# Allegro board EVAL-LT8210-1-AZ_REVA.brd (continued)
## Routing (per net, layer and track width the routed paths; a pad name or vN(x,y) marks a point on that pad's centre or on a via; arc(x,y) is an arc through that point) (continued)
VDD: length 538.3
  TOP w0.635: v2(102.26,104.34) D3.C ; v2(102.26,17.09) D1.C ; v2(102.26,194.13) D5.C ; v2(102.26,283.92) D7.C
  TOP w0.762: RPWGD4.2 47.84,285.54 v1(46.23,283.92) ; v1(46.22,104.33) 47.88,105.99 RPWGD2.2 ; RPWGD3.2 47.85,195.78 v1(46.2,194.13)
  L3_SIG w0.508: v1(46.23,283.92) 46.22,283.91 46.22,194.14 v1(46.2,194.13) 46.22,194.12 v1(46.22,104.33) 46.22,23.36 v2(46.99,22.58)
  L5_VCC w0.508: 46.99,18.08 v2(46.99,22.58) 46.99,29.34 48.77,31.11 v2(52.02,31.11) ; 46.99,18.08 46.99,13.51 ; 46.99,18.08 49.51,18.08 51.23,16.36 JP2.1 ; 46.99,13.51 49.3,13.51 JP1.1 ; 46.99,13.51 46.99,10.74 50.16,7.57 92.73,7.57 v2(102.26,17.09) ; v2(102.26,283.92) 49.25,283.92 v1(46.23,283.92) ; v1(46.22,104.33) 46.88,104.33 46.89,104.34 v2(102.26,104.34) ; v1(46.2,194.13) v2(102.26,194.13)
VIN: length 383.1
  TOP w0.203: L5.1 74.76,90.94 18.16,90.94 P2.1
  TOP w0.508: 28.96,315.25 v2(28.96,316.51) ; 28.96,48.43 28.97,48.44 29.22,48.44 v2(29.22,49.68) ; 28.96,225.46 v2(28.96,226.72) ; v2(28.96,136.65) 28.96,135.65
  TOP w0.61: v2(102.76,200.75) 103.75,200.75 103.76,200.76 RIN3.2 ; RIN1.2 103.76,23.72 103.75,23.71 v2(102.76,23.71) ; v2(102.76,110.96) 103.75,110.96 103.76,110.97 RIN2.2 ; RIN4.2 103.76,290.55 103.75,290.54 v2(102.76,290.54)
  TOP w0.635: REN5.2 103.9,199.13 RIN3.2 ; REN1.2 103.9,22.1 RIN1.2 ; RIN2.2 103.9,109.35 REN3.2 ; REN7.2 103.9,288.92 RIN4.2
  L5_VCC w0.61: 31.62,121.77 91.95,121.77 v2(102.76,110.96) ; 31.55,37.53 88.94,37.53 v2(102.76,23.71) ; v2(102.76,200.75) 91.95,211.56 31.6,211.56 ; v2(102.76,290.54) 91.95,301.35 31.7,301.35
  vias: v2(7.57,273.69) v2(7.57,94.36) v2(8,276.13) v2(8,271.24) v2(8,96.81) v2(8,91.91) v2(9.24,278.29) v2(9.24,269.08) v2(9.24,98.97) v2(9.24,89.76) v2(11.15,279.89) v2(11.15,267.48) v2(11.15,100.56) v2(11.15,88.16) v2(13.49,280.74) v2(13.49,266.63) v2(13.49,101.42) v2(13.49,87.31) v2(15.98,280.74) v2(15.98,266.63) v2(15.98,101.42) v2(15.98,87.31) v2(18.31,279.89) v2(18.31,267.48) v2(18.31,100.56) v2(18.31,88.16) v2(20.22,278.29) v2(20.22,269.08) v2(20.22,98.97) v2(20.22,89.76) v2(21.46,276.13) v2(21.46,271.24) v2(21.46,96.81) v2(21.46,91.91) v2(21.89,273.69) v2(21.89,94.36) v2(24.77,241.68) v2(24.77,240.54) v2(24.77,239.4) v2(24.77,238.25) v2(24.77,237.11) v2(24.77,235.97) v2(24.77,234.82) v2(24.77,233.68) v2(24.77,232.54) v2(24.77,231.39) v2(24.77,230.25) v2(24.77,229.11) v2(24.77,227.97) v2(24.77,226.82) v2(24.77,225.68) v2(24.77,224.54) v2(24.83,331.47) v2(24.83,330.33) v2(24.83,329.18) v2(24.83,328.04) v2(24.83,326.9) v2(24.83,325.75) v2(24.83,324.61) v2(24.83,323.47) v2(24.83,322.33) v2(24.83,321.18) v2(24.83,320.04) v2(24.83,318.9) v2(24.83,317.75) v2(24.83,316.61) v2(24.83,315.47) v2(24.83,314.32) v2(24.89,151.26) v2(24.89,150.11) v2(24.89,148.97) v2(24.89,147.83) v2(24.89,146.69) v2(24.89,145.54) v2(24.89,144.4) v2(24.89,143.26) v2(24.89,142.11) v2(24.89,140.97) v2(24.89,139.83) v2(24.89,138.68) v2(24.89,137.54) v2(24.89,136.4) v2(24.89,135.26) v2(24.89,134.11) v2(24.8,64.01) v2(24.8,62.87) v2(24.8,61.72) v2(24.8,60.58) v2(24.8,59.44) v2(24.8,58.29) v2(24.8,57.15) v2(24.8,56.01) v2(24.8,54.86) v2(24.8,53.72) v2(24.8,52.58) v2(24.8,51.44) v2(24.8,50.29) v2(24.8,49.15) v2(24.8,48.01) v2(24.8,46.86) v2(25.97,331.47) v2(25.97,330.33) v2(25.97,329.18) v2(25.97,328.04) v2(25.97,326.9) v2(25.97,325.75) v2(25.97,324.61) v2(25.97,323.47) v2(25.97,322.33) v2(25.97,321.18) v2(25.97,320.04) v2(25.97,318.9) v2(25.97,317.75) v2(25.97,316.61) v2(25.97,315.47) v2(25.97,314.32) v2(25.91,241.68) v2(25.91,240.54) v2(25.91,239.4) v2(25.91,238.25) v2(25.91,237.11) v2(25.91,235.97) v2(25.91,234.82) v2(25.91,233.68) v2(25.91,232.54) v2(25.91,231.39) v2(25.91,230.25) v2(25.91,229.11) v2(25.91,227.97) v2(25.91,226.82) v2(25.91,225.68) v2(25.91,224.54) v2(25.95,64.01) v2(25.95,62.87) v2(25.95,61.72) v2(25.95,60.58) v2(25.95,59.44) v2(25.95,58.29) v2(25.95,57.15) v2(25.95,56.01) v2(25.95,54.86) v2(25.95,53.72) v2(25.95,52.58) v2(25.95,51.44) v2(25.95,50.29) v2(25.95,49.15) v2(25.95,48.01) v2(25.95,46.86) v2(26.03,151.26) v2(26.03,150.11) v2(26.03,148.97) v2(26.03,147.83) v2(26.03,146.69) v2(26.03,145.54) v2(26.03,144.4) v2(26.03,143.26) v2(26.03,142.11) v2(26.03,140.97) v2(26.03,139.83) v2(26.03,138.68) v2(26.03,137.54) v2(26.03,136.4) v2(26.03,135.26) v2(26.03,134.11) v2(27.05,241.68) v2(27.05,240.54) v2(27.05,239.4) v2(27.05,238.25) v2(27.05,237.11) v2(27.05,235.97) v2(27.05,234.82) v2(27.05,233.68) v2(27.05,232.54) v2(27.05,231.39) v2(27.05,230.25) v2(27.05,229.11) v2(27.05,227.97) v2(27.05,226.82) v2(27.05,225.68) v2(27.05,224.54) v2(27.09,64.01) v2(27.09,62.87) v2(27.09,61.72) v2(27.09,60.58) v2(27.09,59.44) v2(27.09,58.29) v2(27.09,57.15) v2(27.09,56.01) v2(27.09,54.86) v2(27.09,53.72) v2(27.09,52.58) v2(27.09,51.44) v2(27.09,50.29) v2(27.09,49.15) v2(27.09,48.01) v2(27.09,46.86) v2(27.11,331.47) v2(27.11,330.33) v2(27.11,329.18) v2(27.11,328.04) v2(27.11,326.9) v2(27.11,325.75) v2(27.11,324.61) v2(27.11,323.47) v2(27.11,322.33) v2(27.11,321.18) v2(27.11,320.04) v2(27.11,318.9) v2(27.11,317.75) v2(27.11,316.61) v2(27.11,315.47) v2(27.11,314.32) v2(27.18,151.26) v2(27.18,150.11) v2(27.18,148.97) v2(27.18,147.83) v2(27.18,146.69) v2(27.18,145.54) v2(27.18,144.4) v2(27.18,143.26) v2(27.18,142.11) v2(27.18,140.97) v2(27.18,139.83) v2(27.18,138.68) v2(27.18,137.54) v2(27.18,136.4) v2(27.18,135.26) v2(27.18,134.11)
BST1: length 4.1
  TOP w0.635: RBST1.1 111.43,33.95 DBST1.C 109.91,33.93 CBST1.2
BST2: length 4.1
  TOP w0.635: RBST2.1 122.25,33.91 DBST2.C 123.77,33.94 CBST2.1
BST3: length 4.1
  TOP w0.635: CBST3.2 109.91,121.18 DBST3.C 111.43,121.2 RBST3.1
BST4: length 4.1
  TOP w0.635: RBST4.1 122.25,121.16 DBST4.C 123.77,121.19 CBST4.1
BST5: length 4.1
  TOP w0.635: RBST5.1 111.43,210.99 DBST5.C 109.91,210.97 CBST5.2
BST6: length 4.1
  TOP w0.635: CBST6.1 123.77,210.98 DBST6.C 122.25,210.95 RBST6.1
BST7: length 4.1
  TOP w0.635: CBST7.2 109.91,300.76 DBST7.C 111.43,300.77 RBST7.1
BST8: length 4.1
  TOP w0.635: CBST8.1 123.77,300.77 DBST8.C 122.25,300.74 RBST8.1
EN: length 24.9
  TOP w0.508: U8.1 90.76,180.76 R77.2 ; R81.1 R82.1 89.28,189.52 89.28,184.91 87.25,182.88 87.25,181.36 87.84,180.76 R77.2 ; R77.2 87.88,179.62 R80.1 R83.1
EN1: length 247.7
  TOP w0.279: REN1.1 107.1,22.01 107.82,22.73 U1.37
  TOP w0.381: v1(86.99,172.34) 87.08,172.25 R80.2 ; REN2.2 105.69,21.18 v1(105.66,21.21) 105.69,21.23 REN1.1
  L3_SIG w0.381: v1(48.77,170.43) 48.64,170.31 48.64,116.84 47.62,115.82 47.62,108.46 48.77,107.31 48.77,32.89 v1(49.02,32.64)
  L5_VCC w0.381: v1(49.02,32.64) 55.12,32.64 58.55,29.21 89.79,29.21 97.79,21.21 v1(105.66,21.21) ; v1(48.77,170.43) 49.15,170.82 69.72,170.82 71.25,172.34 v1(86.99,172.34)
EN2: length 113.5
  TOP w0.279: U2.37 107.82,109.98 107.1,109.26 REN3.1 v1(105.69,108.46) REN4.2
  TOP w0.381: v1(89.66,171.45) R83.2
  L3_SIG w0.381: v1(105.69,108.46) 89.66,108.46 68.45,129.67 68.45,164.97 74.29,170.82 89.03,170.82 v1(89.66,171.45)
EN3: length 26.7
  TOP w0.279: REN5.1 107.1,199.05 107.82,199.77 U3.37
  TOP w0.381: REN6.2 v1(105.69,198.12) REN5.1 ; v1(91.69,193.04) R81.2
  L3_SIG w0.381: v1(91.69,193.04) 91.82,193.17 103.76,193.17 105.69,195.1 v1(105.69,198.12)
EN4: length 145.9
  TOP w0.279: 105.69,287.88 REN7.1 107.1,288.84 107.82,289.56 U4.37
  TOP w0.381: REN8.2 105.69,287.88 v1(105.66,287.91) ; R82.2 89.79,196.72 v1(88.52,197.99)
  L3_SIG w0.381: v1(90.3,282.32) 91.46,283.48 99.68,283.48 100.2,282.96 102.87,282.96 105.66,285.75 v1(105.66,287.91) ; v1(90.17,279.27) 89.79,278.89 74.93,278.89 66.67,270.64 66.67,238.51 68.45,236.73 68.45,217.55 88.01,197.99 v1(88.52,197.99)
  BOTTOM w0.381: v1(90.3,282.32) 90.17,282.19 v1(90.17,279.27)
EXTVCC_1: length 129.8
  TOP w0.279: U1.25 v1(114.43,29.75) 114.43,30.8 CXVCC1.2
  TOP w0.305: R51.2 93.98,95.85 v1(93.98,94.87)
  L3_SIG w0.305: v1(93.98,94.87) 92.46,93.34 75.18,93.34 68.2,86.36 68.2,59.69 69.72,58.17 v1(69.72,42.67)
  L5_VCC w0.305: v1(114.43,29.75) 114.14,29.75 111.38,32.51 105.79,32.51 95.63,42.67 v1(69.72,42.67)
EXTVCC_2: length 39.3
  TOP w0.279: 114.44,116.47 U2.25 ; 114.44,116.47 v1(114.43,116.46) ; 114.44,116.47 114.44,118.05 CXVCC2.2
  TOP w0.305: R52.2 95.12,97.66 96.14,98.68 96.14,101.98 v1(96.65,102.49)
  L3_SIG w0.305: v1(114.43,116.46) 114.43,115.95 112.78,114.3 108.58,114.3 106.43,112.14 106.43,105.92 103,102.49 v1(96.65,102.49)
EXTVCC_3: length 214.9
  TOP w0.279: CXVCC3.2 114.43,207.84 v1(114.43,205.74) U3.25
  TOP w0.305: v1(95,100.08) 94.36,99.44 R53.2
  L3_SIG w0.305: v1(95,100.08) 57.53,100.08 52.7,104.9 52.7,188.47 54.1,189.87 v1(54.1,203.2)
  L5_VCC w0.305: v1(114.43,205.74) 113.92,205.74 109.35,201.17 106.81,201.17 104.52,198.88 98.3,198.88 93.6,203.58 54.48,203.58 v1(54.1,203.2)
EXTVCC_4: length 277.9
  TOP w0.279: U4.25 v1(114.43,295.78) 114.43,297.63 CXVCC4.2
  TOP w0.305: R54.2 93.94,102.07 94.36,102.49 v1(94.36,103.5)
  L3_SIG w0.305: v1(94.36,103.5) 89.53,103.5 67.18,125.86 67.18,199.52 52.32,214.38 52.32,266.7 66.55,280.92 v1(66.55,293.62)
  L5_VCC w0.305: v1(114.43,295.78) 114.43,295.03 113.28,293.88 110.87,293.88 110.36,293.37 110.36,292.1 106.93,288.67 98.68,288.67 93.73,293.62 v1(66.55,293.62)
FB1: length 574
  TOP w0.508: R63.2 v1(128.48,99.86) ; R59.2 127.29,189.61 v1(129.79,189.61) ; R61.2 128.06,279.44 v1(128.52,279.91) ; R57.2 v1(193.55,137.92) ; R55.2 v1(128.14,12.61)
  L3_SIG w0.508: v1(128.48,99.86) 175.05,99.86 182.12,106.93 182.12,130.05 191.01,138.94 192.53,138.94 v1(193.55,137.92) 193.55,143.76 185.67,151.64 178.56,151.64 177.04,153.16 177.04,178.82 172.09,183.77 132.08,183.77 v1(131.7,184.15) ; v1(128.14,12.61) 160.06,12.61 v1(161.54,14.1) ; v1(188.21,205.74) 187.71,206.25 187.71,266.83 173.61,280.92 129.54,280.92 v1(128.52,279.91)
  L5_VCC w0.508: v1(161.54,14.1) 163.45,14.1 186.31,36.96 186.31,83.44 183.64,86.11 183.64,127.25 193.55,137.16 v1(193.55,137.92) ; v1(188.21,205.74) 171.32,205.74 162.43,196.85 159.51,196.85 153.03,190.37 130.56,190.37 v1(129.79,189.61) 129.79,188.34 131.7,186.44 v1(131.7,184.15)
FB2: length 555.1
  TOP w0.508: v1(125.86,11.81) 125.73,11.94 R56.2 ; R64.2 v1(125.73,98.81) ; v1(125.73,188.72) R60.2 ; R62.2 v1(125.73,278.51) ; v1(191.52,137.8) R58.2
  L3_SIG w0.508: v1(185.55,182.12) 185.55,184.66 183.51,186.69 183.51,200.53 186.37,203.39 186.37,266.51 174.37,278.51 v1(125.73,278.51) ; v1(191.52,137.8) 183.39,129.67 183.39,106.17 175.64,98.42 126.11,98.42 v1(125.73,98.81) ; v1(125.86,11.81) 160.44,11.81 v1(161.75,13.13) ; v1(131.7,188.72) v1(125.73,188.72)
  L5_VCC w0.508: 171.65,180.65 168.53,183.77 134.87,183.77 133.6,185.04 133.6,186.18 131.7,188.09 v1(131.7,188.72) ; 171.65,180.65 184.08,180.65 v1(185.55,182.12) ; 171.65,180.65 176.4,175.9 176.4,153.29 178.56,151.13 185.67,151.13 191.52,145.29 v1(191.52,137.8) 192.66,138.94 194.06,138.94 194.44,138.56 194.44,136.65 184.66,126.87 184.66,86.49 187.2,83.95 187.2,36.45 163.87,13.13 v1(161.75,13.13)
IMON: length 577.6
  TOP w0.305: v1(107.78,189.66) 107.8,189.65 R28.1 ; R8.1 107.8,12.61 v1(107.78,12.62) ; R38.1 107.8,279.44 v1(107.78,279.45) ; v1(107.79,99.87) 107.8,99.86 R18.1 ; IMON.1 v1(141.91,10.21)
  L3_SIG w0.305: v1(107.78,279.45) 107.78,277.08 108.51,276.35 174.75,276.35 185.1,266 185.1,204.15 182.12,201.17 182.12,186.56 ; 182.12,186.56 184.53,184.15 184.53,154.69 194.82,144.4 194.82,130.94 185.1,121.22 185.1,99.39 183.51,97.8 183.51,96.72 ; 182.12,186.56 108.51,186.56 107.78,187.29 v1(107.78,189.66) ; 183.51,96.72 183.46,96.77 108.51,96.77 107.79,97.5 v1(107.79,99.87) ; 183.51,96.72 183.51,90.97 185.1,89.38 185.1,34.48 160.83,10.21 v1(141.91,10.21) 141.21,9.51 108.51,9.51 107.78,10.24 v1(107.78,12.62)
ISN1: length 9.5
  TOP w0.279: U1.15 122.87,23.23 123.4,22.7 C24.2 R7.1 RSNPB1.1
ISN2: length 9.5
  TOP w0.279: RSNPB2.1 R17.1 C48.2 122.89,110.48 U2.15
ISN3: length 9.5
  TOP w0.279: U3.15 122.89,200.27 C72.2 R27.1 RSNPB3.1
ISN4: length 9.5
  TOP w0.279: U4.15 122.89,290.06 C96.2 R37.1 RSNPB4.1
ISP1: length 9.5
  TOP w0.279: RSNPA1.1 R6.1 C24.1 122.85,23.73 U1.16
ISP2: length 9.5
  TOP w0.279: U2.16 122.85,110.98 C48.1 R16.1 RSNPA2.1
ISP3: length 9.5
  TOP w0.279: RSNPA3.1 R26.1 C72.1 122.85,200.77 U3.16
ISP4: length 9.5
  TOP w0.279: RSNPA4.1 R36.1 C96.1 122.85,290.56 U4.16
MODE1: length 559.1
  TOP w0.279: U4.40 109.34,288.06 v1(108.43,288.96) ; U1.40 109.34,21.23 v1(108.43,22.13) ; U3.40 109.34,198.27 v1(108.43,199.17) ; v1(108.43,109.38) 109.34,108.48 U2.40
  L3_SIG w0.279: v1(83.53,18.21) 101.3,18.21 105.22,22.13 v1(108.43,22.13) ; v1(83.79,195.38) 101.42,195.38 105.34,199.29 107.92,199.29 108.04,199.17 v1(108.43,199.17) ; v1(43.89,286.75) 42.72,285.58 v1(42.72,195.36) v1(42.72,113.16) 42.72,18.72 48.62,12.83 51.99,12.83 JP1.2 54.55,12.8 73.48,12.8 v1(78.88,18.2) ; v1(108.43,288.96) 108.04,288.96 107.92,289.08 105.34,289.08 101.64,285.38 v1(83.78,285.38)
  L5_VCC w0.279: v1(83.53,18.21) 83.52,18.2 v1(78.88,18.2) ; JP1.2 JP1.4 ; v1(83.78,285.38) 81.94,285.38 80.57,286.75 v1(43.89,286.75) ; v1(42.72,195.36) 42.74,195.38 v1(83.79,195.38)
  L5_VCC w0.305: v1(42.72,113.16) 45.59,113.16 46.36,113.92 90.55,113.92 95.76,108.71 104.39,108.71 105.06,109.38 v1(108.43,109.38)
MODE2: length 549.2
  TOP w0.279: v1(109.73,109.35) 109.73,109.26 110.01,108.98 U2.39 ; U3.39 109.98,198.77 v1(109.58,199.17) ; U4.39 109.98,288.56 v1(109.58,288.96) ; v1(109.6,22.1) 109.6,22.01 109.88,21.73 U1.39
  L3_SIG w0.279: v1(82.3,19.3) 101.22,19.3 104.65,22.73 108.97,22.73 v1(109.6,22.1) ; v1(109.58,199.17) 109.58,199.54 108.91,200.2 104.85,200.2 101.08,196.43 v1(81.75,196.43) ; v1(45.5,288.23) 45.5,286.84 44.6,285.94 v1(44.6,196.43) v1(44.6,114.81) 44.6,21.31 48.01,17.91 51.73,17.91 JP2.2 53.28,17.34 54.99,19.05 v1(77.09,19.05) ; v1(82.46,286.75) 101.61,286.75 104.85,289.99 108.91,289.99 109.58,289.33 v1(109.58,288.96)
  L5_VCC w0.279: v1(77.09,19.05) 82.04,19.05 v1(82.3,19.3) ; v1(45.5,288.23) 80.99,288.23 81.55,287.67 81.55,287.67 v1(82.46,286.75) ; v1(44.6,114.81) 44.62,114.79 45.15,114.79 45.16,114.81 90.93,114.81 96.39,109.35 104.27,109.35 105.03,110.11 108.97,110.11 v1(109.73,109.35) ; JP2.2 JP2.4 ; v1(81.75,196.43) v1(44.6,196.43)
PWGD1: length 69.2
  TOP w0.279: U1.2 112.43,19.78 112.2,19.55 v1(112.2,19.5)
  TOP w0.762: DS1.C v1(48.49,28.02)
  L5_VCC w0.279: v1(112.2,19.5) 111.56,20.14 95.34,20.14 88.68,26.8 57.54,26.8 56.32,28.02 v1(48.49,28.02)
PWGD2: length 67.7
  TOP w0.279: U2.2 112.44,107.03 v1(112.2,106.8)
  TOP w0.762: DS2.C v1(48.49,111.54)
  L5_VCC w0.279: v1(48.49,111.54) 91.24,111.54 95.34,107.44 111.56,107.44 v1(112.2,106.8)
PWGD3: length 67.7
  TOP w0.279: U3.2 112.43,196.82 v1(112.2,196.59)
  TOP w0.762: DS3.C v1(48.49,201.33)
  L5_VCC w0.279: v1(48.49,201.33) 89.83,201.33 93.95,197.21 111.58,197.21 v1(112.2,196.59)
PWGD4: length 67.7
  TOP w0.279: U4.2 112.43,286.61 v1(112.2,286.38)
  TOP w0.762: DS4.C v1(48.49,291.09)
  L5_VCC w0.279: v1(48.49,291.09) 90.16,291.09 94.25,286.99 111.58,286.99 v1(112.2,286.38)
SYNC1: length 63.2
  TOP w0.203: v1(111.02,19.12) 111.38,19.48 111.38,19.49 111.94,20.04 U1.1
  TOP w0.279: v1(56.91,24.37) 54,24.37 53.21,23.58 U5.4
  L5_VCC w0.279: v1(56.91,24.37) 84.32,24.37 89.57,19.12 v1(111.02,19.12)
SYNC2: length 143
  TOP w0.203: U2.1 111.94,107.33 v1(111.02,106.42)
  TOP w0.279: U5.5 53.7,23.25 54.02,23.57 v1(55.63,23.57)
  L3_SIG w0.203: v1(55.63,23.57) 55.63,32.63 53.09,35.17 53.09,100.53 53.26,100.71 53.39,100.71 v1(53.75,101.07)
  L5_VCC w0.279: v1(111.02,106.42) 108.26,106.42 102.91,101.07 v1(53.75,101.07)
SYNC3: length 231.6
  TOP w0.203: U3.1 111.94,197.12 v1(111.02,196.21)
  TOP w0.279: U5.6 53.7,25.92 54.03,25.6 v1(54.61,25.6)
  L3_SIG w0.203: v1(52.11,190.86) 51.6,190.35 51.6,33.48 54.61,30.47 v1(54.61,25.6)
  L5_VCC w0.279: v1(111.02,196.21) 108.26,196.21 102.91,190.86 v1(52.11,190.86)
SYNC4: length 322.7
  TOP w0.203: U4.1 111.94,286.91 v1(111.02,286)
  TOP w0.279: U5.7 v1(53.21,25.36)
  L3_SIG w0.203: v1(53.21,25.36) 53.21,28.29 50.17,31.32 50.17,280.29 v1(50.53,280.64)
  L5_VCC w0.279: v1(111.02,286) 108.26,286 102.91,280.64 v1(50.53,280.64)
UNNAMED_2_ADLT82101_I27_BG1: length 7.3
  TOP w0.279: RBG1.2 119.23,30.05 117.83,28.65 116.37,28.65 115.43,27.72 U1.23
UNNAMED_2_ADLT82101_I27_BG2: length 7.2
  TOP w0.279: U1.21 116.43,26.93 116.79,27.28 117.68,27.28 120.74,30.34 RBG2.2
UNNAMED_2_ADLT82101_I27_BST1: length 6.6
  TOP w0.279: RBST1.2 111.43,30.53 111.71,30.25 113.16,30.25 113.43,29.97 U1.27
UNNAMED_2_ADLT82101_I27_BST2: length 7.8
  TOP w0.279: RBST2.2 122.25,30.58 117.4,25.73 U1.20
UNNAMED_2_ADLT82101_I27_DG: length 93.9
  TOP w0.279: U1.34 110.27,24.23 v1(109.19,25.31)
  TOP w0.635: R1.2 30.67,43.31 v2(29.87,42.51) DG1.1
  L5_VCC w0.508: v1(109.19,25.31) 94.81,39.7 32.68,39.7 v2(29.87,42.51)
UNNAMED_2_ADLT82101_I27_FB1: length 12.1
  TOP w0.279: U1.11 117.07,19.29 119.13,17.23 121.37,17.23 122.72,15.89 R3C1.1 122.72,14.43 R1A1.2 R1B1.1
UNNAMED_2_ADLT82101_I27_FB2: length 10.4
  TOP w0.279: R2B1.2 R2A1.2 121.08,15.71 R3C1.2 121.02,15.77 120.06,16.74 118.9,16.74 116.44,19.2 116.44,20.59 U1.10
UNNAMED_2_ADLT82101_I27_GATEVCC: length 34.7
  TOP w0.279: CGATE1.1 116.81,30.8 v2(116.81,30.16) 114.93,28.28 U1.24 ; 123,37.52 DBST2.A
  TOP w0.635: v2(123,38.63) 123,37.52 ; v1(110.68,38.56) DBST1.A
  L3_SIG w0.635: v2(123,38.63) 123,32.41 120.75,30.16 v2(116.81,30.16) 115.85,31.13 111.81,31.13 110.68,32.26 v1(110.68,38.56)
UNNAMED_2_ADLT82101_I27_IMON: length 15
  TOP w0.279: U1.7 114.93,17.45 111.86,14.38 CIMON1.1 110.39,14.26 RIMON1.1 R8.2 107.38,14.31 IMON1.1
UNNAMED_2_ADLT82101_I27_RT: length 9.1
  TOP w0.279: RT1.2 110.41,18.88 110.78,18.52 112.29,18.52 112.94,19.16 U1.3
UNNAMED_2_ADLT82101_I27_SNSN1: length 9.3
  TOP w0.279: U1.30 111.94,26.7 107.8,30.84 107.8,31.65 C15.2 108.33,32.26 R4.2
UNNAMED_2_ADLT82101_I27_SNSP1: length 9.8
  TOP w0.279: U1.31 111.3,26.65 107.31,30.64 107.31,31.67 C15.1 106.68,32.31 R3.2
UNNAMED_2_ADLT82101_I27_SS: length 7.8
  TOP w0.279: U1.6 114.43,17.75 112.43,15.75 CSS1.2
UNNAMED_2_ADLT82101_I27_SW1: length 45.4
  TOP w0.279: U1.28 112.94,29.59 112.76,29.77 110.63,29.77 v1(109.91,30.49)
  TOP w0.61: CBST1.1 v1(109.91,30.49)
  L3_SIG w0.61: v1(109.91,30.49) 96.27,44.13 v2(96.27,62.74)
  vias: v2(69.89,68.07) v2(69.89,67.06) v2(69.89,66.04) v2(69.89,65.02) v2(70.88,72.9) v2(70.88,71.63) v2(70.88,70.36) v2(70.88,69.09) v2(71.03,68.07) v2(71.03,67.06) v2(71.03,66.04) v2(71.03,65.02) v2(71.51,72.26) v2(71.51,70.99) v2(71.51,69.72) v2(72.15,72.9) v2(72.15,71.63) v2(72.15,70.36) v2(72.15,69.09) v2(72.17,68.07) v2(72.17,67.06) v2(72.17,66.04) v2(72.17,65.02) v2(72.17,64.01) v2(72.78,72.26) v2(72.78,70.99) v2(72.78,69.72) v2(73.32,68.07) v2(73.32,67.06) v2(73.32,66.04) v2(73.32,65.02) v2(73.32,64.01) v2(73.42,72.9) v2(73.42,71.63) v2(73.42,70.36) v2(73.42,69.09) v2(74.05,72.26) v2(74.05,70.99) v2(74.05,69.72) v2(74.46,68.07) v2(74.46,67.06) v2(74.46,66.04) v2(74.46,65.02) v2(74.46,64.01) v2(74.69,72.9) v2(74.69,71.63) v2(74.69,70.36) v2(74.69,69.09) v2(75.6,68.07) v2(75.6,67.06) v2(75.6,66.04) v2(75.6,65.02) v2(75.6,64.01) v2(83.03,68.07) v2(83.03,67.06) v2(83.9,72.9) v2(83.9,71.63) v2(83.9,70.36) v2(83.9,69.09) v2(84.18,68.07) v2(84.18,67.06) v2(84.53,72.26) v2(84.53,70.99) v2(84.53,69.72) v2(85.17,72.9) v2(85.17,71.63) v2(85.17,70.36) v2(85.17,69.09) v2(85.32,68.07) v2(85.32,67.06) v2(85.32,66.04) v2(85.32,65.02) v2(85.32,64.01) v2(85.8,72.26) v2(85.8,70.99) v2(85.8,69.72) v2(86.44,72.9) v2(86.44,71.63) v2(86.44,70.36) v2(86.44,69.09) v2(86.46,68.07) v2(86.46,67.06) v2(86.46,66.04) v2(86.46,65.02) v2(86.46,64.01) v2(87.07,72.26) v2(87.07,70.99) v2(87.07,69.72) v2(87.6,68.07) v2(87.6,67.06) v2(87.6,66.04) v2(87.6,65.02) v2(87.6,64.01) v2(87.71,72.9) v2(87.71,71.63) v2(87.71,70.36) v2(87.71,69.09) v2(88.61,68.07) v2(88.61,67.06) v2(88.61,66.04) v2(88.61,65.02) v2(88.61,64.01) v2(96.27,72.77) v2(96.27,71.63) v2(96.27,70.48) v2(96.27,69.34) v2(96.27,68.2) v2(96.27,67.06) v2(96.27,65.91) v2(96.27,64.77) v2(96.27,63.75) v2(97.41,72.77) v2(97.41,71.63) v2(97.41,70.48) v2(98.55,72.77) v2(98.55,71.63) v2(98.55,70.48) v2(98.55,65.85) v2(99.69,72.77) v2(99.69,71.63) v2(99.69,70.48) v2(100.84,72.77) v2(100.84,71.63) v2(100.84,70.48) v2(100.84,69.34) v2(100.84,68.2) v2(100.84,67.06) v2(100.84,65.91) v2(100.84,64.77) v2(100.84,63.75) v2(100.84,62.74)
UNNAMED_2_ADLT82101_I27_SW2: length 61
  TOP w0.279: U1.19 117.66,25.23 CBST2.2
  TOP w0.61: v2(124.78,31.34) CBST2.2
  L3_SIG w0.61: v2(149.99,65.91) v2(148.97,65.91) v2(147.83,65.91) v2(146.69,65.91) v2(145.54,65.91) v2(144.41,65.91) 140.21,65.91 124.78,50.48 v2(124.78,31.34)
  vias: v2(123.95,72.77) v2(123.95,71.63) v2(123.95,70.48) v2(123.95,69.34) v2(123.95,68.2) v2(123.95,67.06) v2(125.09,72.77) v2(125.09,71.63) v2(125.09,70.48) v2(125.09,69.34) v2(125.09,68.2) v2(125.09,67.06) v2(126.24,72.77) v2(126.24,71.63) v2(126.24,70.48) v2(126.24,69.34) v2(126.24,68.2) v2(126.24,67.06) v2(127.38,72.77) v2(127.38,71.63) v2(127.38,70.48) v2(127.38,69.34) v2(127.38,68.2) v2(127.38,67.06) v2(127.5,63.12) v2(128.52,72.77) v2(128.52,71.63) v2(128.52,70.48) v2(128.52,69.34) v2(128.52,68.2) v2(128.52,67.06) v2(129.67,72.77) v2(129.67,71.63) v2(129.67,70.48) v2(129.67,69.34) v2(129.67,68.2) v2(129.67,67.06) v2(130.81,72.77) v2(130.81,71.63) v2(130.81,70.48) v2(130.81,69.34) v2(130.81,68.2) v2(130.81,67.06) v2(131.95,72.77) v2(131.95,71.63) v2(131.95,70.48) v2(131.95,69.34) v2(131.95,68.2) v2(131.95,67.06) v2(133.1,72.77) v2(133.1,71.63) v2(133.1,70.48) v2(133.1,69.34) v2(133.1,68.2) v2(133.1,67.06) v2(144.41,67.95) v2(144.41,66.93) v2(144.41,64.9) v2(145.29,72.82) v2(145.29,71.55) v2(145.29,70.28) v2(145.29,69.01) v2(145.54,67.95) v2(145.54,66.93) v2(145.54,64.9) v2(145.92,72.19) v2(145.92,70.92) v2(145.92,69.65) v2(146.56,72.82) v2(146.56,71.55) v2(146.56,70.28) v2(146.56,69.01) v2(146.69,67.95) v2(146.69,66.93) v2(146.69,64.9) v2(147.19,72.19) v2(147.19,70.92) v2(147.19,69.65) v2(147.83,72.82) v2(147.83,71.55) v2(147.83,70.28) v2(147.83,69.01) v2(147.83,67.95) v2(147.83,66.93) v2(147.83,64.9) v2(148.46,72.19) v2(148.46,70.92) v2(148.46,69.65) v2(148.97,67.95) v2(148.97,66.93) v2(148.97,64.9) v2(149.1,72.82) v2(149.1,71.55) v2(149.1,70.28) v2(149.1,69.01) v2(149.99,67.95) v2(149.99,66.93) v2(149.99,64.9) v2(157.4,67.88) v2(157.4,66.87) v2(158.29,72.82) v2(158.29,71.55) v2(158.29,70.28) v2(158.29,69.01) v2(158.42,67.95) v2(158.42,66.93) v2(158.93,72.19) v2(158.93,70.92) v2(158.93,69.65) v2(159.56,72.82) v2(159.56,71.55) v2(159.56,70.28) v2(159.56,69.01) v2(159.56,67.95) v2(159.56,66.93) v2(159.56,65.91) v2(159.56,64.9) v2(159.56,63.88) v2(160.2,72.19) v2(160.2,70.92) v2(160.2,69.65) v2(160.71,67.95) v2(160.71,66.93) v2(160.71,65.91) v2(160.71,64.9) v2(160.71,63.88) v2(160.83,72.82) v2(160.83,71.55) v2(160.83,70.28) v2(160.83,69.01) v2(161.47,72.19) v2(161.47,70.92) v2(161.47,69.65) v2(161.85,67.95) v2(161.85,66.93) v2(161.85,65.91) v2(161.85,64.9) v2(161.85,63.88) v2(162.1,72.82) v2(162.1,71.55) v2(162.1,70.28) v2(162.1,69.01) v2(162.99,67.95) v2(162.99,66.93) v2(162.99,65.91) v2(162.99,64.9) v2(162.99,63.88)
UNNAMED_2_ADLT82101_I27_TG1:
  vias: v2(70.1,63.56) v2(70.1,62.8) v2(83.12,63.56) v2(83.12,62.8) v2(112.13,29.08) v2(112.13,28.45)
UNNAMED_2_ADLT82101_I27_TG2: length 2.3
  TOP w0.279: U1.18 118.08,24.73
  TOP w0.508: 118.08,24.73 v2(119.33,24.73)
  vias: v2(119.33,25.54) v2(120.14,25.54) v2(120.14,24.73) v2(144.53,63.5) v2(144.53,62.74) v2(157.4,63.5) v2(157.4,62.74)
UNNAMED_2_ADLT82101_I27_VC1: length 10.4
  TOP w0.279: U1.8 115.44,20.59 115.44,16.34 RC3.1 114.93,15.66 RC1.2 114.2,13.6 114.2,13.42 R9.2 CP1.2
UNNAMED_2_ADLT82101_I27_VC2: length 10.4
  TOP w0.279: CP2.2 117.98,11.16 R10.1 117.22,13.4 117.22,13.58 RC2.2 116.46,15.66 RC3.2 115.93,16.36 U1.9
UNNAMED_2_ADLT82101_I27_VDD: length 13.4
  TOP w0.279: U1.5 113.94,18.11 112.92,17.09 112.04,17.09
  TOP w0.635: CVDD1.2 105.69,15.07 D1.A 112.04,17.09
UNNAMED_2_ADLT82101_I27_VIN: length 3.7
  TOP w0.279: U1.35 109.79,23.73
  TOP w0.61: RIN1.1 105.68,23.85 105.68,25.91
UNNAMED_2_ADLT82101_I27_VINP: length 9.3
  TOP w0.279: 110.3,25.29 110.86,24.73 U1.33
  TOP w0.61: R2.1 105.62,28.32 C6.2 107.27,28.32 110.3,25.29
UNNAMED_2_ADLT82101_I27_VOUT: length 4.6
  TOP w0.279: U1.13 118.29,22.23
  TOP w0.635: 118.29,22.23 CFOUT1.1 ROUT1.1
UNNAMED_2_ADLTC6902_I7_MOD: length 3.4
  TOP w0.279: U5.9 52.2,28.04 R42.2 R45.1
UNNAMED_2_ADLTC6902_I7_PH: length 3.3
  TOP w0.203: R44.1 R43.2 52.7,20.71 U5.3
UNNAMED_2_ADLTC6902_I7_SET: length 1.9
  TOP w0.279: U5.10 51.71,28.06 R41.2
UNNAMED_2_CAP_I39_N1:
  vias: v1(30.79,58.62) v1(31.04,46.11) v1(31.5,58.62) v1(31.75,46.11)
UNNAMED_2_CAP_I149_N2: length 148.9
  TOP w0.203: v1(121.71,19.18) 121.71,19.19
  TOP w0.279: v2(174.9,45.02) RSNS2.3 ; 121.71,19.19 ROUT1.2 ; R6.2 v1(129.14,24.3)
  L3_SIG w0.203: v1(129.14,24.3) 129.74,23.7 164.11,23.7 176.52,36.11 176.52,43.41 v2(174.9,45.02) 174.94,45.02 176.53,46.61 176.53,55.75 v2(175.26,57.02)
  L3_SIG w0.508: v1(121.71,19.18) 121.71,21.82 128.92,29.03 154.57,29.03 v2(175.22,49.68)
  vias: v2(140.72,59.22) v2(140.72,48.86) v2(144.91,56.26) v2(144.91,55.12) v2(144.91,53.98) v2(145.29,61.14) v2(145.29,59.87) v2(145.29,58.6) v2(145.29,57.33) v2(145.92,60.5) v2(145.92,59.23) v2(145.92,57.96) v2(146.05,56.26) v2(146.05,55.12) v2(146.05,53.98) v2(146.56,61.14) v2(146.56,59.87) v2(146.56,58.6) v2(146.56,57.33) v2(147.07,48.86) v2(147.19,60.5) v2(147.19,59.23) v2(147.19,57.96) v2(147.19,56.26) v2(147.19,55.12) v2(147.19,53.98) v2(147.83,61.14) v2(147.83,59.87) v2(147.83,58.6) v2(147.83,57.33) v2(148.34,56.26) v2(148.34,55.12) v2(148.34,53.98) v2(148.46,60.5) v2(148.46,59.23) v2(148.46,57.96) v2(149.1,61.14) v2(149.1,59.87) v2(149.1,58.6) v2(149.1,57.33) v2(149.48,56.26) v2(149.48,55.12) v2(149.48,53.98) v2(150.62,56.26) v2(150.62,55.12) v2(150.62,53.98) v2(151.76,56.26) v2(151.76,55.12) v2(151.76,53.98) v2(152.91,56.26) v2(152.91,55.12) v2(152.91,53.98) v2(153.42,48.86) v2(153.7,59.09) v2(154.05,56.26) v2(154.05,55.12) v2(154.05,53.98) v2(155.19,56.26) v2(155.19,55.12) v2(155.19,53.98) v2(156.34,56.26) v2(156.34,55.12) v2(156.34,53.98) v2(157.48,56.26) v2(157.48,55.12) v2(157.48,53.98) v2(158.29,61.14) v2(158.29,59.87) v2(158.29,58.6) v2(158.29,57.33) v2(158.62,56.26) v2(158.62,55.12) v2(158.62,53.98) v2(158.93,60.5) v2(158.93,59.23) v2(158.93,57.96) v2(159.56,61.14) v2(159.56,59.87) v2(159.56,58.6) v2(159.56,57.33) v2(159.77,56.26) v2(159.77,55.12) v2(159.77,53.98) v2(160.2,60.5) v2(160.2,59.23) v2(160.2,57.96) v2(160.83,61.14) v2(160.83,59.87) v2(160.83,58.6) v2(160.83,57.33) v2(160.91,56.26) v2(160.91,55.12) v2(160.91,53.98) v2(161.47,60.5) v2(161.47,59.23) v2(161.47,57.96) v2(162.05,56.26) v2(162.05,55.12) v2(162.05,53.98) v2(162.1,61.14) v2(162.1,59.87) v2(162.1,58.6) v2(162.1,57.33) v2(163.89,51.18) v2(166.71,59.09) v2(169.52,56.6) v2(169.52,55.46) v2(169.52,54.32) v2(169.52,53.17) v2(169.52,52.03) v2(169.52,50.89) v2(169.52,49.75) v2(169.52,48.6) v2(169.52,47.59) v2(170.18,60.96) v2(170.18,60.2) v2(170.66,56.6) v2(170.66,55.46) v2(170.66,54.32) v2(170.66,53.17) v2(170.66,52.03) v2(170.66,50.89) v2(170.66,49.75) v2(170.66,48.6) v2(170.66,47.59) v2(170.94,60.96) v2(170.94,60.2) v2(171.42,58.89) v2(171.42,57.75) v2(171.42,56.6) v2(171.42,55.46) v2(171.7,60.96) v2(171.7,60.2) v2(171.81,54.32) v2(172.19,57.75) v2(172.19,56.6) v2(172.19,55.46) v2(172.21,58.8) v2(172.95,61.01) v2(172.95,60.03) v2(172.95,54.32) v2(173.08,50.05) v2(174.09,61.01) v2(174.09,60.03) v2(174.09,54.32) v2(175.23,61.01) v2(175.23,60.03) v2(175.26,59.18) v2(175.23,54.32) v2(175.23,53.17) v2(175.23,52.03) v2(176.02,60.96) v2(176.02,60.07) v2(176.02,59.18)
UNNAMED_2_CAP_I184_N2: length 1.5
  TOP w0.279: RC1.1 CC1.2
UNNAMED_2_CAP_I185_N2: length 1.5
  TOP w0.279: RC2.1 CC2.2
UNNAMED_2_CAPP_I42_N1: length 37.8
  TOP w0.279: v2(101.07,30.48) R2.2
  L3_SIG w0.203: v1(79.76,48.77) 79.76,38.13 87.4,30.48 v2(101.07,30.48)
  vias: v2(33.03,63.2) v2(33.03,61.93) v2(33.03,60.66) v2(33.03,59.39) v2(33.02,57.66) v2(33.02,56.52) v2(33.02,55.37) v2(33.02,54.23) v2(33.02,53.09) v2(33.02,51.94) v2(33.01,50.67) v2(33.01,49.4) v2(33.01,48.13) v2(33.01,46.86) v2(33.67,62.56) v2(33.67,61.29) v2(33.67,60.02) v2(33.64,50.04) v2(33.64,48.77) v2(33.64,47.5) v2(34.16,57.66) v2(34.16,56.52) v2(34.16,55.37) v2(34.16,54.23) v2(34.16,53.09) v2(34.16,51.94) v2(34.28,50.67) v2(34.28,49.4) v2(34.28,48.13) v2(34.28,46.86) v2(34.3,63.2) v2(34.3,61.93) v2(34.3,60.66) v2(34.3,59.39) v2(34.94,62.56) v2(34.94,61.29) v2(34.94,60.02) v2(34.91,50.04) v2(34.91,48.77) v2(34.91,47.5) v2(35.31,57.66) v2(35.31,56.52) v2(35.31,55.37) v2(35.31,54.23) v2(35.31,53.09) v2(35.31,51.94) v2(35.57,63.2) v2(35.57,61.93) v2(35.57,60.66) v2(35.57,59.39) v2(35.55,50.67) v2(35.55,49.4) v2(35.55,48.13) v2(35.55,46.86) v2(36.18,50.04) v2(36.18,48.77) v2(36.18,47.5) v2(36.21,62.56) v2(36.21,61.29) v2(36.21,60.02) v2(36.45,57.66) v2(36.45,56.52) v2(36.45,55.37) v2(36.45,54.23) v2(36.45,53.09) v2(36.45,51.94) v2(36.84,63.2) v2(36.84,61.93) v2(36.84,60.66) v2(36.84,59.39) v2(36.82,50.67) v2(36.82,49.4) v2(36.82,48.13) v2(36.82,46.86) v2(37.92,69.97) v2(47.5,46.61) v2(54.36,61.34) v2(54.36,60.2) v2(54.36,59.05) v2(54.36,57.91) v2(54.36,56.77) v2(54.36,55.63) v2(54.36,54.48) v2(54.36,53.34) v2(54.36,52.2) v2(54.36,51.05) v2(54.36,49.91) v2(54.36,48.77) v2(54.36,47.75) v2(54.36,46.74) v2(55.5,61.34) v2(55.5,60.2) v2(55.5,59.05) v2(55.5,57.91) v2(55.5,56.77) v2(55.5,55.63) v2(55.5,54.48) v2(55.8,69.85) v2(56.64,61.34) v2(56.64,60.2) v2(56.64,59.05) v2(56.64,57.91) v2(56.64,56.77) v2(56.64,55.63) v2(56.64,54.48) v2(56.62,49.99) v2(57.79,61.34) v2(57.79,60.2) v2(57.79,59.05) v2(57.79,57.91) v2(57.79,56.77) v2(57.79,55.63) v2(57.79,54.48) v2(58.93,61.34) v2(58.93,60.2) v2(58.93,59.05) v2(58.93,57.91) v2(58.93,56.77) v2(58.93,55.63) v2(58.93,54.48) v2(58.93,53.34) v2(58.93,52.2) v2(58.93,51.05) v2(58.93,49.91) v2(58.93,48.77) v2(58.93,47.75) v2(58.93,46.74) v2(61.85,61.34) v2(61.85,60.2) v2(61.85,59.05) v2(61.85,57.91) v2(61.85,56.77) v2(61.85,55.63) v2(61.85,54.48) v2(61.85,53.34) v2(61.85,52.2) v2(61.85,51.05) v2(61.85,49.91) v2(61.85,48.77) v2(61.85,47.75) v2(61.85,46.74) v2(62.99,61.34) v2(62.99,60.2) v2(62.99,59.05) v2(62.99,57.91) v2(62.99,56.77) v2(62.99,55.63) v2(62.99,54.48) v2(64.08,49.99) v2(64.13,57.91) v2(64.13,56.77) v2(64.13,55.63) v2(64.13,54.48) v2(65.28,57.91) v2(65.28,56.77) v2(65.28,55.63) v2(65.28,54.48) v2(66.18,59.22) v2(66.42,57.91) v2(66.42,56.77) v2(66.42,55.63) v2(66.42,54.48) v2(66.42,53.34) v2(66.42,52.2) v2(66.42,51.05) v2(66.42,49.91) v2(66.42,48.77) v2(66.42,47.75) v2(66.42,46.74) v2(70.9,61.38) v2(70.9,60.11) v2(70.9,58.84) v2(70.9,57.57) v2(70.99,56.39) v2(70.99,55.24) v2(70.99,54.1) v2(71.54,60.74) v2(71.54,59.47) v2(71.54,58.2) v2(72.17,61.38) v2(72.17,60.11) v2(72.17,58.84) v2(72.17,57.57) v2(72.14,56.39) v2(72.14,55.24) v2(72.14,54.1) v2(72.81,60.74) v2(72.81,59.47) v2(72.81,58.2) v2(73.15,51.06) v2(73.28,56.39) v2(73.28,55.24) v2(73.28,54.1) v2(73.44,61.38) v2(73.44,60.11) v2(73.44,58.84) v2(73.44,57.57) v2(74.08,60.74) v2(74.08,59.47) v2(74.08,58.2) v2(74.42,56.39) v2(74.42,55.24) v2(74.42,54.1) v2(74.71,61.38) v2(74.71,60.11) v2(74.71,58.84) v2(74.71,57.57) v2(75.56,56.39) v2(75.56,55.24) v2(75.56,54.1) v2(76.71,56.39) v2(76.71,55.24) v2(76.71,54.1) v2(77.85,56.39) v2(77.85,55.24) v2(77.85,54.1) v2(78.99,56.39) v2(78.99,55.24) v2(78.99,54.1) v2(79.3,59.22) v2(80.14,56.39) v2(80.14,55.24) v2(80.14,54.1) v2(81.28,56.39) v2(81.28,55.24) v2(81.28,54.1) v2(82.42,56.39) v2(82.42,55.24) v2(82.42,54.1) v2(83.57,56.39) v2(83.57,55.24) v2(83.57,54.1) v2(83.82,48.98) v2(83.92,61.38) v2(83.92,60.11) v2(83.92,58.84) v2(83.92,57.57) v2(84.56,60.74) v2(84.56,59.47) v2(84.56,58.2) v2(84.71,56.39) v2(84.71,55.24) v2(84.71,54.1) v2(85.19,61.38) v2(85.19,60.11) v2(85.19,58.84) v2(85.19,57.57) v2(85.83,60.74) v2(85.83,59.47) v2(85.83,58.2) v2(85.85,56.39) v2(85.85,55.24) v2(85.85,54.1) v2(86.46,61.38) v2(86.46,60.11) v2(86.46,58.84) v2(86.46,57.57) v2(86.99,56.39) v2(86.99,55.24) v2(86.99,54.1) v2(87.1,60.74) v2(87.1,59.47) v2(87.1,58.2) v2(87.73,61.38) v2(87.73,60.11) v2(87.73,58.84) v2(87.73,57.57) v2(88.14,56.39) v2(88.14,55.24) v2(88.14,54.1) v2(90.17,48.98) v2(92.4,59.33) v2(97.54,48.98) v2(103.76,48.98)
UNNAMED_2_DIOLED_I8_P: length 1.5
  TOP w0.762: RPWGD1.1 DS1.A
UNNAMED_2_IND_I187_N1:
  vias: v2(103.76,72.77) v2(103.76,71.63) v2(103.76,70.48) v2(103.76,69.34) v2(103.76,68.2) v2(103.76,67.06) v2(103.76,65.91) v2(103.76,64.77) v2(103.76,63.75) v2(103.76,62.74) v2(104.9,72.77) v2(104.9,71.63) v2(104.9,70.48) v2(106.04,72.77) v2(106.04,71.63) v2(106.04,70.48) v2(106.02,65.85) v2(107.19,71.63) v2(107.19,70.48) v2(108.33,70.48) v2(108.33,69.34) v2(108.33,68.2) v2(108.33,67.06) v2(108.33,65.91) v2(108.33,64.77) v2(108.33,63.75) v2(108.33,62.74) v2(111.76,72.77) v2(111.76,71.63) v2(111.76,70.48) v2(111.76,69.34) v2(111.76,68.2) v2(111.76,67.06) v2(112.9,72.77) v2(112.9,71.63) v2(112.9,70.48) v2(112.9,69.34) v2(112.9,68.2) v2(112.9,67.06) v2(114.05,72.77) v2(114.05,71.63) v2(114.05,70.48) v2(114.05,69.34) v2(114.05,68.2) v2(114.05,67.06) v2(115.19,72.77) v2(115.19,71.63) v2(115.19,70.48) v2(115.19,69.34) v2(115.19,68.2) v2(115.19,67.06) v2(116.33,72.77) v2(116.33,71.63) v2(116.33,70.48) v2(116.33,69.34) v2(116.33,68.2) v2(116.33,67.06) v2(117.35,63.12) v2(117.47,72.77) v2(117.47,71.63) v2(117.47,70.48) v2(117.47,69.34) v2(117.47,68.2) v2(117.47,67.06) v2(118.62,72.77) v2(118.62,71.63) v2(118.62,70.48) v2(118.62,69.34) v2(118.62,68.2) v2(118.62,67.06) v2(119.76,72.77) v2(119.76,71.63) v2(119.76,70.48) v2(119.76,69.34) v2(119.76,68.2) v2(119.76,67.06) v2(120.9,72.77) v2(120.9,71.63) v2(120.9,70.48) v2(120.9,69.34) v2(120.9,68.2) v2(120.9,67.06)
UNNAMED_2_NCTESTPAD_I95_N1:
  vias: v1(118.73,34.59) v1(118.73,33.78) v1(119.46,34.59) v1(119.46,33.78) v2(70,75.13) v2(70,74.37) v2(83.03,75.12) v2(83.03,74.36)
UNNAMED_2_NCTESTPAD_I107_N1:
  vias: v1(120.5,34.59) v1(120.5,33.78) v1(121.25,34.59) v1(121.25,33.78) v2(144.4,74.93) v2(144.4,74.17) v2(157.4,74.93) v2(157.4,74.17)
UNNAMED_2_RES_I50_N2: length 96.6
  TOP w0.279: RSNPA1.2 v2(127.46,25.83) ; RSNS3.3 v2(58.6,45.03)
  L3_SIG w0.254: v2(58.6,45.03) 60.1,43.54 60.1,38.76 60.12,38.73 60.12,38.44 84.88,13.68 120.97,13.68 128.12,20.83 128.12,25.17 v2(127.46,25.83)
UNNAMED_2_RES_I54_N2: length 89.9
  TOP w0.279: RSNS3.1 v2(62.1,45.03) ; v2(127.46,21.19) 126.57,21.19 RSNPB1.2
  L3_SIG w0.254: v2(127.46,21.19) 120.41,14.14 85.07,14.14 60.58,38.63 60.58,43.51 v2(62.1,45.03)
UNNAMED_2_RES_I97_N1: length 30.5
  TOP w0.279: RSNS1.3 v1(100.48,60.9) ; R3.1 v1(106.68,36.2)
  L3_SIG w0.203: v1(106.68,36.2) 106.74,36.2 107.24,36.7 107.24,37.08 102.1,42.22 102.1,59.28 v1(100.48,60.9)
UNNAMED_2_RES_I103_N1: length 30.6
  TOP w0.279: R4.1 v1(108.33,36.2) ; RSNS1.1 v1(104.09,60.9)
  L3_SIG w0.203: v1(104.09,60.9) 102.5,59.31 102.5,42.39 107.75,37.14 107.75,36.67 108.22,36.2 v1(108.33,36.2)
UNNAMED_2_RES_I137_N1: length 8.3
  TOP w0.305: v1(127.25,15.11) R55.1
  TOP w0.508: 122.63,11.99 v1(122.68,11.94) ; 122.63,11.99 R1A1.1 ; 122.63,11.99 R1C1.1
  L3_SIG w0.305: v1(127.25,15.11) 126.49,14.35 124.84,14.35 122.68,12.19 v1(122.68,11.94)
UNNAMED_2_RES_I140_N1: length 8.2
  TOP w0.305: 121.08,11.99 v1(121.03,11.94) ; v1(125.73,15.11) R56.1
  TOP w0.508: R2C1.1 R2A1.1
  L3_SIG w0.305: v1(121.03,11.94) 124.21,15.11 v1(125.73,15.11)
UNNAMED_3_ADLT82101_I10_BG1: length 7.3
  TOP w0.279: RBG5.2 119.23,207.09 117.83,205.69 116.37,205.69 115.43,204.75 U3.23
UNNAMED_3_ADLT82101_I10_BG2: length 7.2
  TOP w0.279: U3.21 116.43,203.96 116.79,204.32 117.68,204.32 120.74,207.38 RBG6.2
UNNAMED_3_ADLT82101_I10_BST1: length 6.6
  TOP w0.279: RBST5.2 111.43,207.57 111.71,207.29 113.16,207.29 113.43,207.01 U3.27
UNNAMED_3_ADLT82101_I10_BST2: length 7.9
  TOP w0.279: RBST6.2 122.25,207.56 117.46,202.77 U3.20
UNNAMED_3_ADLT82101_I10_DG: length 93.9
  TOP w0.279: U3.34 110.27,201.27 v1(109.19,202.35)
  TOP w0.635: R21.2 30.67,220.29 v2(29.92,219.54) DG3.1
  L5_VCC w0.508: v2(29.92,219.54) 34.96,214.5 97.04,214.5 v1(109.19,202.35)
UNNAMED_3_ADLT82101_I10_FB1: length 12.1
  TOP w0.279: R1B3.1 R1A3.2 122.72,191.46 R3C3.1 122.72,192.93 121.37,194.27 119.13,194.27 117.07,196.33 U3.11
UNNAMED_3_ADLT82101_I10_FB2: length 10.5
  TOP w0.279: R2B3.2 R2A3.2 121.08,192.81 R3C3.2 121.02,192.94 120.18,193.78 118.9,193.78 116.43,196.24 U3.10
UNNAMED_3_ADLT82101_I10_GATEVCC: length 34.5
  TOP w0.279: 123,214.56 DBST6.A ; CGATE3.1 116.81,207.84 v2(116.81,207.2) 114.93,205.32 U3.24
  TOP w0.635: v2(123,215.66) 123,214.56 ; v1(110.68,215.6) DBST5.A
  L3_SIG w0.61: v1(110.68,215.6) 110.68,209.48 111.99,208.17 115.85,208.17 v2(116.81,207.2) 120.63,207.2 123,209.58 v2(123,215.66)
UNNAMED_3_ADLT82101_I10_IMON: length 15
  TOP w0.279: IMON3.1 107.38,191.35 R28.2 RIMON3.1 110.39,191.3 CIMON3.1 111.86,191.41 114.93,194.49 U3.7
UNNAMED_3_ADLT82101_I10_RT: length 9.1
  TOP w0.279: U3.3 112.94,196.2 112.34,195.61 110.78,195.61 110.46,195.92 RT3.2
UNNAMED_3_ADLT82101_I10_SNSN1: length 9.3
  TOP w0.279: U3.30 111.94,203.74 107.8,207.87 107.8,208.68 C63.2 108.33,209.29 R24.2
UNNAMED_3_ADLT82101_I10_SNSP1: length 9.8
  TOP w0.279: U3.31 111.3,203.69 107.31,207.67 107.31,208.71 C63.1 106.68,209.34 R23.2
UNNAMED_3_ADLT82101_I10_SS: length 7.8
  TOP w0.279: CSS3.2 112.43,192.79 114.43,194.79 U3.6
UNNAMED_3_ADLT82101_I10_SW1: length 45.4
  TOP w0.279: v1(109.91,207.53) 110.63,206.81 112.76,206.81 112.94,206.63 U3.28
  TOP w0.61: v1(109.91,207.53) CBST5.1
  L3_SIG w0.61: v2(96.27,239.78) 96.27,221.17 v1(109.91,207.53)
  vias: v2(69.89,245.11) v2(69.89,244.09) v2(69.89,243.08) v2(69.89,242.06) v2(70.88,249.94) v2(70.88,248.67) v2(70.88,247.4) v2(70.88,246.13) v2(71.03,245.11) v2(71.03,244.09) v2(71.03,243.08) v2(71.03,242.06) v2(71.51,249.3) v2(71.51,248.03) v2(71.51,246.76) v2(72.15,249.94) v2(72.15,248.67) v2(72.15,247.4) v2(72.15,246.13) v2(72.17,245.11) v2(72.17,244.09) v2(72.17,243.08) v2(72.17,242.06) v2(72.17,241.05) v2(72.78,249.3) v2(72.78,248.03) v2(72.78,246.76) v2(73.32,245.11) v2(73.32,244.09) v2(73.32,243.08) v2(73.32,242.06) v2(73.32,241.05) v2(73.42,249.94) v2(73.42,248.67) v2(73.42,247.4) v2(73.42,246.13) v2(74.05,249.3) v2(74.05,248.03) v2(74.05,246.76) v2(74.46,245.11) v2(74.46,244.09) v2(74.46,243.08) v2(74.46,242.06) v2(74.46,241.05) v2(74.69,249.94) v2(74.69,248.67) v2(74.69,247.4) v2(74.69,246.13) v2(75.6,245.11) v2(75.6,244.09) v2(75.6,243.08) v2(75.6,242.06) v2(75.6,241.05) v2(83.03,245.11) v2(83.03,244.09) v2(83.9,249.94) v2(83.9,248.67) v2(83.9,247.4) v2(83.9,246.13) v2(84.18,245.11) v2(84.18,244.09) v2(84.53,249.3) v2(84.53,248.03) v2(84.53,246.76) v2(85.17,249.94) v2(85.17,248.67) v2(85.17,247.4) v2(85.17,246.13) v2(85.32,245.11) v2(85.32,244.09) v2(85.32,243.08) v2(85.32,242.06) v2(85.32,241.05) v2(85.8,249.3) v2(85.8,248.03) v2(85.8,246.76) v2(86.44,249.94) v2(86.44,248.67) v2(86.44,247.4) v2(86.44,246.13) v2(86.46,245.11) v2(86.46,244.09) v2(86.46,243.08) v2(86.46,242.06) v2(86.46,241.05) v2(87.07,249.3) v2(87.07,248.03) v2(87.07,246.76) v2(87.6,245.11) v2(87.6,244.09) v2(87.6,243.08) v2(87.6,242.06) v2(87.6,241.05) v2(87.71,249.94) v2(87.71,248.67) v2(87.71,247.4) v2(87.71,246.13) v2(88.58,245.11) v2(88.58,244.09) v2(88.58,243.08) v2(88.58,242.06) v2(88.58,241.05) v2(96.27,249.81) v2(96.27,248.67) v2(96.27,247.52) v2(96.27,246.38) v2(96.27,245.24) v2(96.27,244.09) v2(96.27,242.95) v2(96.27,241.81) v2(96.27,240.79) v2(97.41,249.81) v2(97.41,248.67) v2(97.41,247.52) v2(98.55,249.81) v2(98.55,248.67) v2(98.55,247.52) v2(98.55,242.93) v2(99.69,249.81) v2(99.69,248.67) v2(99.69,247.52) v2(100.84,249.81) v2(100.84,248.67) v2(100.84,247.52) v2(100.84,246.38) v2(100.84,245.24) v2(100.84,244.09) v2(100.84,242.95) v2(100.84,241.81) v2(100.84,240.79) v2(100.84,239.78)
UNNAMED_3_ADLT82101_I10_SW2: length 61
  TOP w0.279: CBST6.2 117.66,202.27 U3.19
  TOP w0.61: v2(124.78,208.38) CBST6.2
  L3_SIG w0.61: v2(149.99,242.95) v2(148.97,242.95) v2(147.83,242.95) v2(146.69,242.95) v2(145.54,242.95) v2(144.4,242.95) 140.21,242.95 124.78,227.52 v2(124.78,208.38)
  vias: v2(123.95,249.81) v2(123.95,248.67) v2(123.95,247.52) v2(123.95,246.38) v2(123.95,245.24) v2(123.95,244.09) v2(125.09,249.81) v2(125.09,248.67) v2(125.09,247.52) v2(125.09,246.38) v2(125.09,245.24) v2(125.09,244.09) v2(126.24,249.81) v2(126.24,248.67) v2(126.24,247.52) v2(126.24,246.38) v2(126.24,245.24) v2(126.24,244.09) v2(127.38,249.81) v2(127.38,248.67) v2(127.38,247.52) v2(127.38,246.38) v2(127.38,245.24) v2(127.38,244.09) v2(127.5,240.15) v2(128.52,249.81) v2(128.52,248.67) v2(128.52,247.52) v2(128.52,246.38) v2(128.52,245.24) v2(128.52,244.09) v2(129.67,249.81) v2(129.67,248.67) v2(129.67,247.52) v2(129.67,246.38) v2(129.67,245.24) v2(129.67,244.09) v2(130.81,249.81) v2(130.81,248.67) v2(130.81,247.52) v2(130.81,246.38) v2(130.81,245.24) v2(130.81,244.09) v2(131.95,249.81) v2(131.95,248.67) v2(131.95,247.52) v2(131.95,246.38) v2(131.95,245.24) v2(131.95,244.09) v2(133.1,249.81) v2(133.1,248.67) v2(133.1,247.52) v2(133.1,246.38) v2(133.1,245.24) v2(133.1,244.09) v2(144.4,244.98) v2(144.4,243.97) v2(144.4,241.93) v2(145.29,249.86) v2(145.29,248.59) v2(145.29,247.32) v2(145.29,246.05) v2(145.54,244.98) v2(145.54,243.97) v2(145.54,241.93) v2(145.92,249.22) v2(145.92,247.95) v2(145.92,246.68) v2(146.56,249.86) v2(146.56,248.59) v2(146.56,247.32) v2(146.56,246.05) v2(146.69,244.98) v2(146.69,243.97) v2(146.69,241.93) v2(147.19,249.22) v2(147.19,247.95) v2(147.19,246.68) v2(147.83,249.86) v2(147.83,248.59) v2(147.83,247.32) v2(147.83,246.05) v2(147.83,244.98) v2(147.83,243.97) v2(147.83,241.93) v2(148.46,249.22) v2(148.46,247.95) v2(148.46,246.68) v2(148.97,244.98) v2(148.97,243.97) v2(148.97,241.93) v2(149.1,249.86) v2(149.1,248.59) v2(149.1,247.32) v2(149.1,246.05) v2(149.99,244.98) v2(149.99,243.97) v2(149.99,241.93) v2(157.42,244.94) v2(157.42,243.93) v2(158.29,249.86) v2(158.29,248.59) v2(158.29,247.32) v2(158.29,246.05) v2(158.42,244.98) v2(158.42,243.97) v2(158.93,249.22) v2(158.93,247.95) v2(158.93,246.68) v2(159.56,249.86) v2(159.56,248.59) v2(159.56,247.32) v2(159.56,246.05) v2(159.56,244.98) v2(159.56,243.97) v2(159.56,242.95) v2(159.56,241.93) v2(159.56,240.92) v2(160.2,249.22) v2(160.2,247.95) v2(160.2,246.68) v2(160.71,244.98) v2(160.71,243.97) v2(160.71,242.95) v2(160.71,241.93) v2(160.71,240.92) v2(160.83,249.86) v2(160.83,248.59) v2(160.83,247.32) v2(160.83,246.05) v2(161.47,249.22) v2(161.47,247.95) v2(161.47,246.68) v2(161.85,244.98) v2(161.85,243.97) v2(161.85,242.95) v2(161.85,241.93) v2(161.85,240.92) v2(162.1,249.86) v2(162.1,248.59) v2(162.1,247.32) v2(162.1,246.05) v2(162.98,244.98) v2(162.98,243.97) v2(162.98,242.95) v2(162.98,241.93) v2(162.98,240.92)
UNNAMED_3_ADLT82101_I10_TG1:
  vias: v2(70.08,240.6) v2(70.08,239.84) v2(83.09,240.61) v2(83.09,239.85) v2(112.13,206.12) v2(112.13,205.49)
UNNAMED_3_ADLT82101_I10_TG2: length 2.3
  TOP w0.279: U3.18 118.08,201.77
  TOP w0.508: 118.08,201.77 v2(119.33,201.77)
  vias: v2(119.33,202.58) v2(120.14,202.58) v2(120.14,201.77) v2(144.58,240.54) v2(144.58,239.78) v2(157.58,240.41) v2(157.58,239.65)
UNNAMED_3_ADLT82101_I10_VC1: length 10.4
  TOP w0.279: U3.8 115.43,193.37 RC9.1 114.93,192.7 RC7.2 114.2,190.64 114.2,190.46 R29.2 CP5.2
UNNAMED_3_ADLT82101_I10_VC2: length 10.4
  TOP w0.279: CP6.2 117.98,188.2 R30.1 117.22,190.44 117.22,190.61 RC8.2 116.46,192.7 RC9.2 115.93,193.4 U3.9
UNNAMED_3_ADLT82101_I10_VDD: length 13.4
  TOP w0.279: 106.72,194.13 112.92,194.13 113.94,195.15 U3.5
  TOP w0.635: 106.72,194.13 D5.A 105.69,192.11 CVDD3.2
UNNAMED_3_ADLT82101_I10_VIN: length 3.7
  TOP w0.279: U3.35 109.79,200.77
  TOP w0.61: 105.68,202.95 105.68,200.89 RIN3.1
UNNAMED_3_ADLT82101_I10_VINP: length 9.3
  TOP w0.279: U3.33 110.86,201.77 110.3,202.32
  TOP w0.61: R22.1 105.62,205.36 C54.2 107.27,205.36 110.3,202.32
UNNAMED_3_ADLT82101_I10_VOUT: length 4.6
  TOP w0.279: U3.13 118.29,199.27
  TOP w0.635: ROUT3.1 CFOUT3.1 118.29,199.27
UNNAMED_3_CAP_I22_N1:
  vias: v1(30.79,235.66) v1(30.86,223.14) v1(31.5,235.66) v1(31.57,223.13)
UNNAMED_3_CAP_I128_N2: length 150.5
  TOP w0.203: v1(121.71,196.19) 121.71,196.19 121.71,196.25 121.71,196.25 ; R66.1 v2(175.13,233.81)
  TOP w0.279: ROUT3.2 121.71,196.25 ; v2(174.9,222.05) RSNS8.3 ; R26.2 v1(129.14,201.34)
  L3_SIG w0.203: v2(175.13,233.81) 176.4,232.54 176.4,223.55 v2(174.9,222.05) 176.5,220.45 176.5,212.78 164.47,200.74 129.74,200.74 v1(129.14,201.34)
  L3_SIG w0.508: v1(121.71,196.19) 121.71,198.83 129.67,206.79 155.04,206.79 v2(175.22,226.97)
  vias: v2(140.72,236.26) v2(140.72,225.89) v2(144.91,233.3) v2(144.91,232.16) v2(144.91,231.01) v2(145.29,238.18) v2(145.29,236.91) v2(145.29,235.64) v2(145.29,234.37) v2(145.92,237.54) v2(145.92,236.27) v2(145.92,235) v2(146.05,233.3) v2(146.05,232.16) v2(146.05,231.01) v2(146.56,238.18) v2(146.56,236.91) v2(146.56,235.64) v2(146.56,234.37) v2(147.07,225.89) v2(147.19,237.54) v2(147.19,236.27) v2(147.19,235) v2(147.19,233.3) v2(147.19,232.16) v2(147.19,231.01) v2(147.83,238.18) v2(147.83,236.91) v2(147.83,235.64) v2(147.83,234.37) v2(148.34,233.3) v2(148.34,232.16) v2(148.34,231.01) v2(148.46,237.54) v2(148.46,236.27) v2(148.46,235) v2(149.1,238.18) v2(149.1,236.91) v2(149.1,235.64) v2(149.1,234.37) v2(149.48,233.3) v2(149.48,232.16) v2(149.48,231.01) v2(150.62,233.3) v2(150.62,232.16) v2(150.62,231.01) v2(151.76,233.3) v2(151.76,232.16) v2(151.76,231.01) v2(152.91,233.3) v2(152.91,232.16) v2(152.91,231.01) v2(153.42,225.89) v2(153.7,236.13) v2(154.05,233.3) v2(154.05,232.16) v2(154.05,231.01) v2(155.19,233.3) v2(155.19,232.16) v2(155.19,231.01) v2(156.34,233.3) v2(156.34,232.16) v2(156.34,231.01) v2(157.48,233.3) v2(157.48,232.16) v2(157.48,231.01) v2(158.24,238.11) v2(158.29,236.91) v2(158.29,235.64) v2(158.29,234.37) v2(158.62,233.3) v2(158.62,232.16) v2(158.62,231.01) v2(158.93,237.54) v2(158.93,236.27) v2(158.93,235) v2(159.56,238.18) v2(159.56,236.91) v2(159.56,235.64) v2(159.56,234.37) v2(159.77,233.3) v2(159.77,232.16) v2(159.77,231.01) v2(160.2,237.54) v2(160.2,236.27) v2(160.2,235) v2(160.83,238.18) v2(160.83,236.91) v2(160.83,235.64) v2(160.83,234.37) v2(160.91,233.3) v2(160.91,232.16) v2(160.91,231.01) v2(161.47,237.54) v2(161.47,236.27) v2(161.47,235) v2(162.05,233.3) v2(162.05,232.16) v2(162.05,231.01) v2(162.1,238.18) v2(162.1,236.91) v2(162.1,235.64) v2(162.1,234.37) v2(163.88,228.22) v2(166.71,236.13) v2(169.49,231.36) v2(169.49,230.21) v2(169.49,229.07) v2(169.49,227.93) v2(169.49,226.78) v2(169.49,225.64) v2(169.49,224.5) v2(170.31,238.25) v2(170.31,237.49) v2(170.31,236.73) v2(170.64,231.36) v2(170.64,230.21) v2(170.64,229.07) v2(170.64,227.93) v2(170.64,226.78) v2(170.64,225.64) v2(170.64,224.5) v2(170.89,235.93) v2(170.89,234.78) v2(170.89,233.64) v2(170.89,232.5) v2(171.07,238.25) v2(171.07,237.49) v2(171.07,236.73) v2(171.78,238.21) v2(171.78,237.07) v2(171.78,231.36) v2(172.03,235.93) v2(172.03,234.78) v2(172.03,233.64) v2(172.03,232.5) v2(172.92,238.21) v2(172.92,237.07) v2(172.92,231.36) v2(173,227.01) v2(174.07,238.21) v2(174.07,237.07) v2(174.07,231.36) v2(175.13,236.35) v2(175.21,238.21) v2(175.21,237.07) v2(175.21,231.36) v2(175.21,230.21) v2(175.21,229.07) v2(175.89,236.35)
UNNAMED_3_CAP_I151_N2: length 1.5
  TOP w0.279: RC7.1 CC5.2
UNNAMED_3_CAP_I154_N2: length 1.5
  TOP w0.279: RC8.1 CC6.2
UNNAMED_3_CAPP_I25_N1: length 37.6
  TOP w0.279: v2(101.07,207.52) R22.2
  L3_SIG w0.203: v2(101.07,207.52) 87.4,207.52 80.26,214.66 v1(80.26,225.81)
  vias: v2(33.02,240.23) v2(33.02,238.96) v2(33.02,237.69) v2(33.02,236.42) v2(33.02,234.7) v2(33.02,233.55) v2(33.02,232.41) v2(33.02,231.27) v2(33.02,230.12) v2(33.02,228.98) v2(33.02,227.71) v2(33.02,226.44) v2(33.02,225.17) v2(33.02,223.9) v2(33.66,239.6) v2(33.66,238.33) v2(33.66,237.06) v2(33.66,227.08) v2(33.66,225.81) v2(33.66,224.54) v2(34.16,234.7) v2(34.16,233.55) v2(34.16,232.41) v2(34.16,231.27) v2(34.16,230.12) v2(34.16,228.98) v2(34.29,240.23) v2(34.29,238.96) v2(34.29,237.69) v2(34.29,236.42) v2(34.29,227.71) v2(34.29,226.44) v2(34.29,225.17) v2(34.29,223.9) v2(34.92,239.6) v2(34.92,238.33) v2(34.92,237.06) v2(34.92,227.08) v2(34.92,225.81) v2(34.92,224.54) v2(35.31,234.7) v2(35.31,233.55) v2(35.31,232.41) v2(35.31,231.27) v2(35.31,230.12) v2(35.31,228.98) v2(35.56,240.23) v2(35.56,238.96) v2(35.56,237.69) v2(35.56,236.42) v2(35.56,227.71) v2(35.56,226.44) v2(35.56,225.17) v2(35.56,223.9) v2(36.2,239.6) v2(36.2,238.33) v2(36.2,237.06) v2(36.2,227.08) v2(36.2,225.81) v2(36.2,224.54) v2(36.45,234.7) v2(36.45,233.55) v2(36.45,232.41) v2(36.45,231.27) v2(36.45,230.12) v2(36.45,228.98) v2(36.83,240.23) v2(36.83,238.96) v2(36.83,237.69) v2(36.83,236.42) v2(36.83,227.71) v2(36.83,226.44) v2(36.83,225.17) v2(36.83,223.9) v2(37.92,247.01) v2(47.5,223.65) v2(54.36,238.38) v2(54.36,237.24) v2(54.36,236.09) v2(54.36,234.95) v2(54.36,233.81) v2(54.36,232.66) v2(54.36,231.52) v2(54.36,230.38) v2(54.36,229.23) v2(54.36,228.09) v2(54.36,226.95) v2(54.36,225.81) v2(54.36,224.79) v2(54.36,223.77) v2(55.5,238.38) v2(55.5,237.24) v2(55.5,236.09) v2(55.5,234.95) v2(55.5,233.81) v2(55.5,232.66) v2(55.5,231.52) v2(55.8,246.88) v2(56.64,238.38) v2(56.64,237.24) v2(56.64,236.09) v2(56.64,234.95) v2(56.64,233.81) v2(56.64,232.66) v2(56.64,231.52) v2(56.62,227.02) v2(57.79,238.38) v2(57.79,237.24) v2(57.79,236.09) v2(57.79,234.95) v2(57.79,233.81) v2(57.79,232.66) v2(57.79,231.52) v2(58.93,238.38) v2(58.93,237.24) v2(58.93,236.09) v2(58.93,234.95) v2(58.93,233.81) v2(58.93,232.66) v2(58.93,231.52) v2(58.93,230.38) v2(58.93,229.23) v2(58.93,228.09) v2(58.93,226.95) v2(58.93,225.81) v2(58.93,224.79) v2(58.93,223.77) v2(61.85,238.38) v2(61.85,237.24) v2(61.85,236.09) v2(61.85,234.95) v2(61.85,233.81) v2(61.85,232.66) v2(61.85,231.52) v2(61.85,230.38) v2(61.85,229.23) v2(61.85,228.09) v2(61.85,226.95) v2(61.85,225.81) v2(61.85,224.79) v2(61.85,223.77) v2(62.99,238.38) v2(62.99,237.24) v2(62.99,236.09) v2(62.99,234.95) v2(62.99,233.81) v2(62.99,232.66) v2(62.99,231.52) v2(64.08,227.02) v2(64.13,234.95) v2(64.13,233.81) v2(64.13,232.66) v2(64.13,231.52) v2(65.28,234.95) v2(65.28,233.81) v2(65.28,232.66) v2(65.28,231.52) v2(66.18,236.26) v2(66.42,234.95) v2(66.42,233.81) v2(66.42,232.66) v2(66.42,231.52) v2(66.42,230.38) v2(66.42,229.23) v2(66.42,228.09) v2(66.42,226.95) v2(66.42,225.81) v2(66.42,224.79) v2(66.42,223.77) v2(70.9,238.43) v2(70.9,237.16) v2(70.9,235.89) v2(70.9,234.62) v2(70.99,233.43) v2(70.99,232.28) v2(70.99,231.14) v2(71.54,237.79) v2(71.54,236.52) v2(71.54,235.25) v2(72.17,238.43) v2(72.17,237.16) v2(72.17,235.89) v2(72.17,234.62) v2(72.14,233.43) v2(72.14,232.28) v2(72.14,231.14) v2(72.81,237.79) v2(72.81,236.52) v2(72.81,235.25) v2(73.15,228.09) v2(73.28,233.43) v2(73.28,232.28) v2(73.28,231.14) v2(73.44,238.43) v2(73.44,237.16) v2(73.44,235.89) v2(73.44,234.62) v2(74.08,237.79) v2(74.08,236.52) v2(74.08,235.25) v2(74.42,233.43) v2(74.42,232.28) v2(74.42,231.14) v2(74.71,238.43) v2(74.71,237.16) v2(74.71,235.89) v2(74.71,234.62) v2(75.56,233.43) v2(75.56,232.28) v2(75.56,231.14) v2(76.71,233.43) v2(76.71,232.28) v2(76.71,231.14) v2(77.85,233.43) v2(77.85,232.28) v2(77.85,231.14) v2(78.99,233.43) v2(78.99,232.28) v2(78.99,231.14) v2(79.3,236.26) v2(80.14,233.43) v2(80.14,232.28) v2(80.14,231.14) v2(81.28,233.43) v2(81.28,232.28) v2(81.28,231.14) v2(82.42,233.43) v2(82.42,232.28) v2(82.42,231.14) v2(83.57,233.43) v2(83.57,232.28) v2(83.57,231.14) v2(83.82,226.02) v2(83.92,238.42) v2(83.92,237.15) v2(83.92,235.88) v2(83.92,234.61) v2(84.56,237.78) v2(84.56,236.51) v2(84.56,235.24) v2(84.71,233.43) v2(84.71,232.28) v2(84.71,231.14) v2(85.19,238.42) v2(85.19,237.15) v2(85.19,235.88) v2(85.19,234.61) v2(85.83,237.78) v2(85.83,236.51) v2(85.83,235.24) v2(85.85,233.43) v2(85.85,232.28) v2(85.85,231.14) v2(86.46,238.42) v2(86.46,237.15) v2(86.46,235.88) v2(86.46,234.61) v2(86.99,233.43) v2(86.99,232.28) v2(86.99,231.14) v2(87.1,237.78) v2(87.1,236.51) v2(87.1,235.24) v2(87.73,238.42) v2(87.73,237.15) v2(87.73,235.88) v2(87.73,234.61) v2(88.14,233.43) v2(88.14,232.28) v2(88.14,231.14) v2(90.17,226.02) v2(92.3,236.26) v2(97.54,226.02) v2(103.76,226.02)
